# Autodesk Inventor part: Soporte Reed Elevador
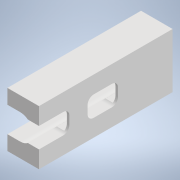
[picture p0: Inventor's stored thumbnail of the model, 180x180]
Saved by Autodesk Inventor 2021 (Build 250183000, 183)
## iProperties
Created: 2021-03
Part Number: Soporte Reed Elevador
Material: Genérico
Document SubType Name: Modeling
Designer: ATOUZA
Density: 1 g/cm^3
Appearance: Valor por defecto
Author: ATOUZA
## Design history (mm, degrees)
sketch "Boceto1"
  geometry: L1 (0.791, -1.4)-(1.963, -1.4) reference; L2 (1.963, -1.4)-(1.963, 1.4) reference; L3 (1.963, 1.4)-(0.791, 1.4) reference; L4 (0.833, 1.5)-(2.063, 1.5); L5 (2.063, 1.5)-(2.063, -1.5); L6 (2.063, -1.5)-(0.833, -1.5); L7 (-0.637, 2.1)-(-2.737, 2.1); L8 (-2.737, 2.1)-(-2.737, 4.5); L9 (-2.737, 4.5)-(2.463, 4.5); L10 (2.463, 4.5)-(2.463, 0); L11 (3.393, 0)-(-3.545, 0); L12 (2.063, 0)-(2.063, 1.5); L13 (0.833, 1.5)-(2.063, 1.5); L14 (-0.637, -2.1)-(-2.737, -2.1); L15 (0.833, -1.5)-(2.063, -1.5); L16 (2.063, 0)-(2.063, -1.5); L17 (2.463, -4.5)-(2.463, 0); L18 (-2.737, -4.5)-(2.463, -4.5); L19 (-2.737, -2.1)-(-2.737, -4.5); A1 r 2 centre (-0.637, 0) between (0.791, 1.4) and (0.791, -1.4) reference; A2 r 2.1 centre (-0.637, 0) between (0.833, 1.5) and (0.833, -1.5); A3 r 2.1 centre (-0.637, 0) between (0.833, 1.5) and (-0.637, 2.1); A4 r 2.1 centre (-0.637, 0) between (-0.637, -2.1) and (0.833, -1.5); 1 further point
  constraints: 32 end point, 7 point on circle, 4 perpendicular, 4 symmetric about line, 3 centre point, 3 tangent, 2 collinear, 2 horizontal, 2 point on line, 1 midpoint, 4 other
  dimensions: "d0" = 0.1 radial gap between concentric circles of A1 A2; "d2" = 5.2 distance of L8.end L9.end; "d3" = 4.5 distance between parallel lines of L9 L11
extrude "Extrusión1" new body sketch "Boceto1" distance "d4" = 22; taper "d5" = 0 deg
sketch "Boceto2"
  geometry: L1 (1.501, 5.424)-(2.924, 4.001) reference; L2 (2.499, 3.576)-(1.076, 4.999) reference; L3 (1.501, 5.424)-(2.924, 4.001); L4 (2.499, 3.576)-(1.076, 4.999); L5 (7, 4.1)-(7, 4.9); L6 (9.6, 3.7)-(7.4, 3.7); L7 (10, 4.9)-(10, 4.1); L8 (7.4, 5.3)-(9.6, 5.3); L9 (7, 4.1)-(7, 4.9); L10 (7.4, 5.3)-(9.6, 5.3); L11 (10, 4.9)-(10, 4.1); L12 (9.6, 3.7)-(7.4, 3.7); L13 (0, 3.1)-(0, 5.9); L14 (0, 3.1)-(22, 3.1); L15 (22, 5.9)-(22, 3.1); L16 (0, 5.9)-(22, 5.9); L17 (0, 6.173)-(22, 6.173); L18 (0, 2.827)-(22, 2.827); L19 (5, 6.173)-(8, 6.173); L20 (8, 6.173)-(8, 2.827); L21 (8, 2.827)-(5, 2.827); L22 (5, 2.827)-(5, 6.173); L23 (13, 6.173)-(22, 6.173); L24 (22, 2.827)-(13, 2.827); L25 (13, 2.827)-(13, 6.173); L26 (0, 2.827)-(0, 6.173); L27 (0, 6)-(0, 3) reference; C1 r 1.25 at (2, 4.5) reference; C2 r 1.25 at (2, 4.5); C3 r 1.25 at (2, 4.5); A1 r 1.05 centre (2, 4.5) between (1.076, 4.999) and (2.499, 3.576) reference; A2 r 1.05 centre (2, 4.5) between (2.924, 4.001) and (1.501, 5.424); A3 r 1.05 centre (2, 4.5) between (1.076, 4.999) and (2.499, 3.576); A4 r 0.4 centre (7.4, 4.1) between (7, 4.1) and (7.4, 3.7); A5 r 0.4 centre (9.6, 4.1) between (9.6, 3.7) and (10, 4.1); A6 r 0.4 centre (9.6, 4.9) between (10, 4.9) and (9.6, 5.3); A7 r 0.4 centre (7.4, 4.9) between (7.4, 5.3) and (7, 4.9); A8 r 0.4 centre (7.4, 4.1) between (7, 4.1) and (7.4, 3.7); A9 r 0.4 centre (7.4, 4.9) between (7.4, 5.3) and (7, 4.9); A10 r 0.4 centre (9.6, 4.9) between (10, 4.9) and (9.6, 5.3); A11 r 0.4 centre (9.6, 4.1) between (9.6, 3.7) and (10, 4.1); 15 further points
  constraints: 48 end point, 20 point on circle, 12 centre point, 3 parallel, 3 point on line, 2 horizontal, 1 collinear, 1 perpendicular
  dimensions: "d9" = 9 distance between parallel lines of L15 L25; "d10" = 5 distance between parallel lines of L20 L25; "d11" = 3 distance between parallel lines of L20 L22
extrude "Extrusión2" cut sketch "Boceto2" extent not by distance; stored distance "d12" = 0; taper "d13" = 0 deg
fillet "Empalme1" dims "d14" = 1
node "Sólido1"
node "Referencia1"
node "Referencia2"
node "Referencia3"
node "Referencia4"
node "Referencia5"
